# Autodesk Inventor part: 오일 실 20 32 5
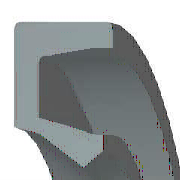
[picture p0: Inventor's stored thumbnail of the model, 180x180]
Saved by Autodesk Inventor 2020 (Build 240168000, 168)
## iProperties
IsCustomPart: 1
Created: 2012-02
Part Number: 오일 실 20 32 5
Material: 고무
Description: 오일 실 - 비스프링, 금속 케이스 GM
Document SubType Name: Modeling
Standard: JIS B 2402
Designer: mdu-01
Standards Organization: JIS
Language: ko-KR
Size Designation: 20 32 5 A
Categories: <MemberInstance><Categories><Category DisplayName="샤프트 부품" InternalName="7f7aeb1f-a693-4053-b835-cee3144e0d98" Mnemonic="SHFT"><Category DisplayName="실링" Intern
Density: 0.93 g/cm^3
Appearance: Rubber-Black
Author: mdu-01
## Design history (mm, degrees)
body "Solid1"
revolve "회전1" stored, may be unused: angle "d27" = 360 deg
fillet "모깎기1" dims "d28" = 0.25 (= 0.05 x b)
chamfer "모따기1" distance "d29" = 0.07143 (= 0.0142857 x b); stored, may be unused: second distance "d30" = 0.25 (= 0.05 x b), angle "d35" = 45 deg
sketch "스케치2"
  geometry: L1 (-10.8, -3.238)-(-11.6, -3.863); L2 (-10, -1.625)-(-10.8, -3.238); L3 (-10.6, -1)-(-10, -1.625); L4 (-12.6, -3.75)-(-10.6, -1); L5 (-14.175, -3.75)-(-12.6, -3.75); L6 (-15.375, -1.25)-(-14.175, -3.75); L7 (-15.375, 0)-(-15.375, -1.25); L8 (-16, 0)-(-15.375, 0); L9 (-16, -5)-(-16, 0); L10 (-12.427, -5)-(-16, -5); L11 (-11.6, -3.863)-(-12.427, -5); L12 (0, -9.6)-(0, 1.6) reference; L13 (-14, 0)-(-28, 0) reference
  constraints: 22 end point, 3 horizontal, 2 vertical, 1 parallel
  dimensions: "d2" = 5 distance of L9.start L8.start (= b); "d4" = 1 vertical distance of L8.start L3.start (= 0.2 x b); "d6" = 0.625 distance of L8.start L7.start (= 0.125 x b); "d8" = 1.25 distance of L7.start L6.start (= 0.25 x b); "d10" = 1.25 vertical distance of L5.start L9.start (= 0.25 x b); "d12" = 1.2 horizontal distance of L6.start L5.start (= 0.1 x dd - 0.1 x Diam); "d14" = 1.6129 vertical distance of L2.start L1.start (= 0.322581 x b); "d16" = 0.8 horizontal distance of L1.start L1.end (= 0.0666667 x dd - 0.0666667 x Diam); "d18" = 0.8 horizontal distance of L2.start L1.start (= 0.0666667 x dd - 0.0666667 x Diam); "d20" = 0.625 vertical distance of L3.start L2.start (= 0.125 x b); "d22" = 0.6 horizontal distance of L3.start L2.start (= 0.05 x dd - 0.05 x Diam); "d24" = 0.625 vertical distance of L1.start L1.end (= 0.125 x b); "d26" = 2 horizontal distance of L4.start L3.start (= 0.166667 x dd - 0.166667 x Diam); "d31" = 0 distance between parallel lines of L8 L13; "d32" = 16 distance between parallel lines of L12 L9 (= 0.5 x dd); "d33" = 10 distance from line of L12 L2.start (= 0.5 x Diam)
other parameters: "dd" = 32 [user parameter; used in 6 equation terms], "b" = 5 [user parameter; used in 11 equation terms], "d1" = 8 (derived), "d3" = 1.6 (derived), "d5" = 1 (derived), "d7" = 2 (derived), "d9" = 2 (derived), "d11" = 2 (derived), "d13" = 2.58065 (derived), "d15" = 1.33333 (derived), "d17" = 1.33333 (derived), "d19" = 1 (derived), "d21" = 1 (derived), "d23" = 1 (derived), "d25" = 3.33333 (derived), "d34" = 0
